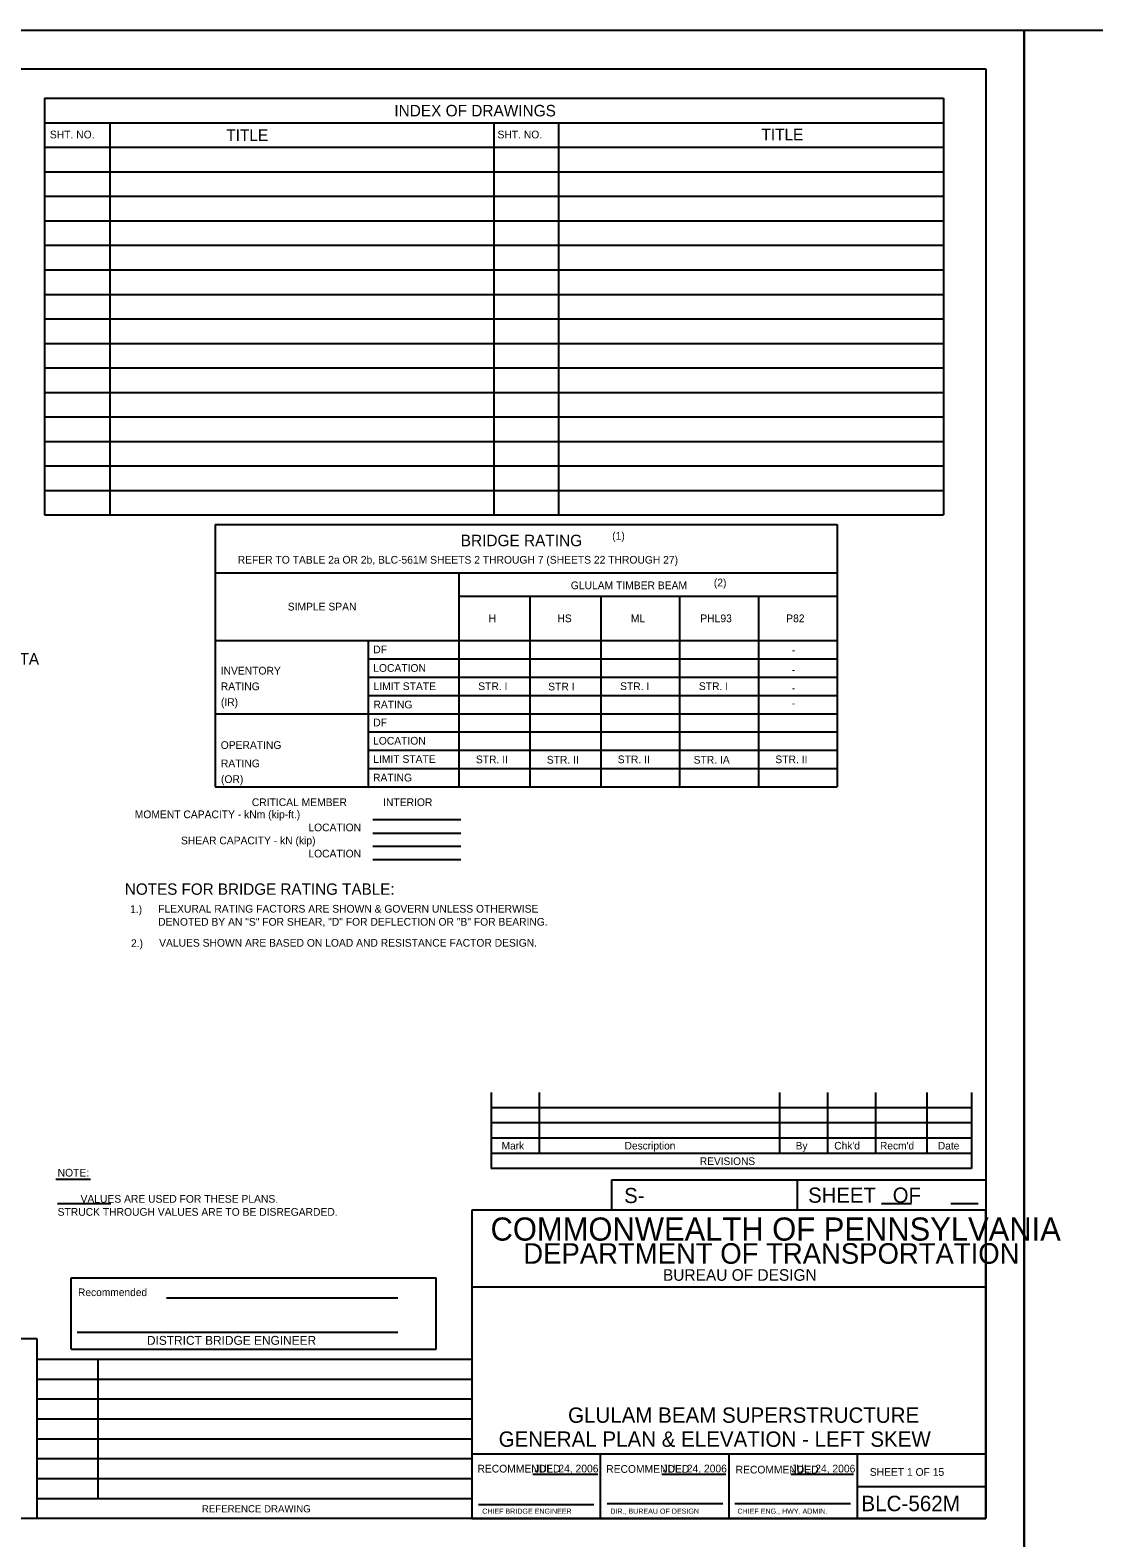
# Model space of a CAD drawing. Extents: x 638263 to 640360, y 293683 to 298655.
# Drawn here: x 638889 to 639304, y 297849 to 298435 of the extents above; entities that cross this region are included whole.
import ezdxf

# ---------------------------------------------------------------- set-up
doc = ezdxf.new("R2010")
doc.units = 0
for name, color, linetype in [('2', 7, 'Continuous'), ('4', 7, 'Continuous'), ('7', 7, 'Continuous'), ('PLT-BNDY', 7, 'Continuous')]:
    doc.layers.add(name, color=color, linetype=linetype)

msp = doc.modelspace()

# ---------------------------------------------------------------- linework, layer by layer
at = {"layer": '2'}
for p, q in [((638475.46, 298420.46), (639261.46, 298420.46)), ((639261.46, 298420.46), (639261.46, 297856.46)), ((639068.92, 298022.15), (639068.92, 297992.62)), ((639087.62, 298022.15), (639087.62, 297998.53)), ((639181.13, 298022.15), (639181.13, 297998.53)), ((639199.83, 298022.15), (639199.83, 297998.53)), ((639218.53, 298022.15), (639218.53, 297998.53)), ((639238.59, 298022.15), (639238.59, 297998.53)), ((639255.94, 298022.15), (639255.94, 297992.62)), ((639255.94, 298016.24), (639068.92, 298016.24)), ((639255.94, 298010.34), (639068.92, 298010.34)), ((639255.94, 298004.43), (639068.92, 298004.43)), ((639255.94, 297998.53), (639068.92, 297998.53)), ((639255.94, 297992.62), (639068.92, 297992.62)), ((638899.44, 297988.52), (638913.01, 297988.52)), ((639261.46, 297988.11), (639115.78, 297988.11)), ((639115.78, 297988.11), (639115.78, 297976.46)), ((639188.09, 297988.11), (639188.09, 297976.46)), ((638900.17, 297979.08), (638920.87, 297979.08)), ((639220.95, 297979), (639232.6, 297979)), ((639247.83, 297979), (639258.56, 297979)), ((639261.46, 297976.46), (639061.46, 297976.46)), ((639061.46, 297976.46), (639061.46, 297856.46)), ((639261.46, 297856.46), (639261.46, 297976.46)), ((638905.4, 297922.31), (638905.4, 297950.1)), ((638905.4, 297950.1), (639047.58, 297950.1)), ((639047.58, 297922.31), (639047.58, 297950.1)), ((638942.6, 297942.38), (639032.62, 297942.38)), ((639261.46, 297946.46), (639061.46, 297946.46)), ((638907.84, 297929.02), (639032.62, 297929.02)), ((638905.4, 297922.31), (639047.58, 297922.31)), ((639261.46, 297881.46), (639061.46, 297881.46)), ((639111.46, 297856.46), (639111.46, 297881.46)), ((639161.46, 297881.46), (639161.46, 297856.46)), ((639211.46, 297881.46), (639211.46, 297856.46)), ((639085.11, 297873.75), (639110.49, 297873.75)), ((639135.38, 297873.75), (639160.27, 297873.75)), ((639185.65, 297873.75), (639210.06, 297873.75)), ((639211.46, 297868.96), (639261.46, 297868.96)), ((639063.96, 297861.96), (639108.96, 297861.96)), ((639114.08, 297862.33), (639159.08, 297862.33)), ((639163.83, 297862.33), (639208.83, 297862.33)), ((639261.46, 297856.46), (638475.46, 297856.46)), ((639061.46, 297856.46), (639261.46, 297856.46))]:
    msp.add_line(p, q, dxfattribs=at)
at = {"layer": '4'}
for p, q in [((638895.05, 298408.97), (639245.05, 298408.97)), ((638895.05, 298408.97), (638895.05, 298246.86)), ((639245.05, 298408.97), (639245.05, 298246.86)), ((638895.05, 298399.44), (639070.05, 298399.44)), ((638920.52, 298399.44), (638920.52, 298246.86)), ((639070.05, 298399.44), (639245.05, 298399.44)), ((639070.05, 298399.44), (639070.05, 298246.86)), ((639095.21, 298399.44), (639095.21, 298246.86)), ((638895.05, 298389.9), (639070.05, 298389.9)), ((639070.05, 298389.9), (639245.05, 298389.9)), ((638895.05, 298380.36), (639070.05, 298380.36)), ((639070.05, 298380.36), (639245.05, 298380.36)), ((638895.05, 298370.83), (639070.05, 298370.83)), ((639070.05, 298370.83), (639245.05, 298370.83)), ((638895.05, 298361.29), (639070.05, 298361.29)), ((639070.05, 298361.29), (639245.05, 298361.29)), ((638895.05, 298351.76), (639070.05, 298351.76)), ((639070.05, 298351.76), (639245.05, 298351.76)), ((638895.05, 298342.22), (639070.05, 298342.22)), ((639070.05, 298342.22), (639245.05, 298342.22)), ((638895.05, 298332.68), (639070.05, 298332.68)), ((639070.05, 298332.68), (639245.05, 298332.68)), ((638895.05, 298323.15), (639070.05, 298323.15)), ((639070.05, 298323.15), (639245.05, 298323.15)), ((638895.05, 298313.61), (639070.05, 298313.61)), ((639070.05, 298313.61), (639245.05, 298313.61)), ((638895.05, 298304.08), (639070.05, 298304.08)), ((639070.05, 298304.08), (639245.05, 298304.08)), ((638895.05, 298294.54), (639070.05, 298294.54)), ((639070.05, 298294.54), (639245.05, 298294.54)), ((638895.05, 298285.01), (639070.05, 298285.01)), ((639070.05, 298285.01), (639245.05, 298285.01)), ((638895.05, 298275.47), (639070.05, 298275.47)), ((639070.05, 298275.47), (639245.05, 298275.47)), ((638895.05, 298265.93), (639070.05, 298265.93)), ((639070.05, 298265.93), (639245.05, 298265.93)), ((638895.05, 298256.4), (639070.05, 298256.4)), ((639070.05, 298256.4), (639245.05, 298256.4)), ((638895.05, 298246.86), (639245.05, 298246.86)), ((639021.04, 298190.91), (639203.67, 298190.91)), ((639021.04, 298183.8), (639203.67, 298183.8)), ((639021.04, 298176.68), (639203.67, 298176.68)), ((639021.04, 298162.45), (639203.67, 298162.45)), ((639021.04, 298155.33), (639203.67, 298155.33)), ((639021.04, 298148.22), (639203.67, 298148.22)), ((639022.83, 298128.43), (639057.1, 298128.43)), ((639022.83, 298123.11), (639057.1, 298123.11)), ((639022.83, 298118.06), (639057.1, 298118.06)), ((639022.83, 298112.88), (639057.1, 298112.88)), ((638892.25, 297926.31), (638754.05, 297926.31)), ((638892.25, 297856.46), (638892.25, 297926.31)), ((639061.46, 297918.34), (638892.25, 297918.34)), ((638915.96, 297864.19), (638915.96, 297918.34)), ((639061.46, 297910.6), (638892.25, 297910.6)), ((639061.46, 297902.87), (638892.25, 297902.87)), ((639061.46, 297895.13), (638892.25, 297895.13)), ((639061.46, 297887.4), (638892.25, 297887.4)), ((639061.46, 297879.66), (638892.25, 297879.66)), ((639061.46, 297871.93), (638892.25, 297871.93)), ((639061.46, 297864.19), (638892.25, 297864.19))]:
    msp.add_line(p, q, dxfattribs=at)
at = {"layer": '7'}
for p, q in [((638961.55, 298243.11), (638961.55, 298141.1)), ((638961.55, 298243.11), (639203.67, 298243.11)), ((639203.67, 298243.11), (639203.67, 298141.1)), ((638961.55, 298224.41), (639203.67, 298224.41)), ((639056.4, 298224.41), (639056.4, 298141.1)), ((639056.4, 298215.21), (639203.67, 298215.21)), ((639084.01, 298215.21), (639084.01, 298141.1)), ((639111.62, 298215.21), (639111.62, 298141.1)), ((639142.31, 298215.21), (639142.31, 298141.1)), ((639172.99, 298215.21), (639172.99, 298141.1)), ((638961.55, 298198.03), (639203.67, 298198.03)), ((639021.04, 298198.03), (639021.04, 298141.1)), ((638961.55, 298169.56), (639203.67, 298169.56)), ((638961.55, 298141.1), (639203.67, 298141.1))]:
    msp.add_line(p, q, dxfattribs=at)
at = {"layer": 'PLT-BNDY'}
for points in [[(638435.46, 298435.46), (639276.46, 298435.46), (639276.46, 297841.46), (638435.46, 297841.46)], [(639276.46, 298435.46), (640117.46, 298435.46), (640117.46, 297841.46), (639276.46, 297841.46)]]:
    msp.add_lwpolyline(points, close=True, dxfattribs=at)

# ---------------------------------------------------------------- texts
at = {"layer": '2'}
for s, height, p in [('MOMENT CAPACITY - kNm (kip-ft.)', 3, (638930.2, 298128.9)), ('LOCATION', 3, (638997.8, 298123.81)), ('SHEAR CAPACITY - kN (kip)', 3, (638948.2, 298118.73)), ('LOCATION', 3, (638997.8, 298113.64)), ('Mark', 2.952, (639073.02, 298000.03)), ('Description', 2.9523, (639120.92, 298000.03)), ('By', 2.952, (639187.49, 298000.03)), ("Chk'd", 2.952, (639202.52, 298000.03)), ("Recm'd", 2.953, (639220.33, 298000.03)), ('Date', 2.952, (639242.86, 298000.03)), ('REVISIONS', 2.952, (639150.2, 297994.01)), ('NOTE:', 3, (638900.18, 297989.5)), ('S-', 5.905, (639120.73, 297979.17)), ('STRUCK THROUGH VALUES ARE TO BE DISREGARDED.', 3, (638900.18, 297974.25)), ('        VALUES ARE USED FOR THESE PLANS.  ', 3, (638900.18, 297979.33)), ('COMMONWEALTH OF PENNSYLVANIA', 9, (639068.71, 297964.58)), ('DEPARTMENT OF TRANSPORTATION', 8.0002, (639081.46, 297955.58)), ('BUREAU OF DESIGN', 4.5, (639135.83, 297948.96)), ('Recommended', 2.9682, (638908.11, 297943)), ('GENERAL PLAN & ELEVATION - LEFT SKEW', 5.9728, (639071.87, 297884.37)), ('RECOMMENDED', 3, (639063.61, 297874.37)), ('JUL. 24, 2006', 3, (639085.74, 297874.4)), ('RECOMMENDED', 3, (639113.74, 297874.25)), ('JUL. 24, 2006', 3, (639135.74, 297874.4)), ('RECOMMENDED', 3, (639164.11, 297874)), ('JUL. 24, 2006', 3, (639185.74, 297874.4)), ('SHEET 1 OF 15', 3, (639216.33, 297873.08)), ('CHIEF BRIDGE ENGINEER', 2.0002, (639065.46, 297858.33)), ('DIR., BUREAU OF DESIGN', 2.0002, (639115.33, 297858.33)), ('CHIEF ENG., HWY. ADMIN.', 2.0002, (639164.83, 297858.33)), ('BLC-562M', 6, (639213.08, 297859.33))]:
    msp.add_text(s, height=height, dxfattribs=at).set_placement(p)
for s, height, rotation, p in [('SHEET   OF', 5.907, 360, (639192.35, 297979.31)), ('DISTRICT BRIDGE ENGINEER', 3.4629, 359.99999, (638934.95, 297924.04))]:
    msp.add_text(s, height=height, rotation=rotation, dxfattribs=at).set_placement(p)
at = {"layer": '4'}
for s, height, p in [('INDEX OF DRAWINGS', 4.4792, (639031.26, 298401.91)), ('SHT. NO.', 3, (638897.16, 298393.36)), ('TITLE', 4.479, (638965.83, 298392.37)), ('SHT. NO.', 3, (639071.42, 298393.36)), ('TITLE', 4.479, (639174.17, 298392.63)), ('BRIDGE RATING', 4.4792, (639057.11, 298234.7)), ('(1)', 3, (639116.06, 298237.25)), ('REFER TO TABLE 2a OR 2b, BLC-561M SHEETS 2 THROUGH 7 (SHEETS 22 THROUGH 27)', 3, (638970.28, 298227.93)), ('GLULAM TIMBER BEAM', 3, (639099.95, 298217.98)), ('(2)', 3, (639155.64, 298219.05)), ('SIMPLE SPAN', 3, (638989.75, 298209.71)), ('H', 3, (639067.96, 298205.15)), ('HS', 3, (639094.73, 298205.15)), ('ML', 3, (639123.32, 298205.15)), ('PHL93', 3, (639150.37, 298205.15)), ('P82', 3, (639183.81, 298205.15)), ('DF', 3, (639023.05, 298193.04)), ('HYDRAULIC DATA', 4.4292, (638841.27, 298188.69)), ('LOCATION', 3, (639023.05, 298185.85)), ('-', 3, (639186, 298192.82)), ('INVENTORY', 3, (638963.66, 298184.8)), ('-', 3, (639186, 298185.21)), ('RATING', 3, (638963.7, 298178.7)), ('LIMIT STATE', 3, (639023.16, 298178.74)), ('STR. I', 3, (639063.91, 298178.74)), ('STR I', 3, (639091.15, 298178.61)), ('STR. I', 3, (639119.13, 298178.75)), ('STR. I', 3, (639149.81, 298178.75)), ('-', 3, (639186, 298178.1)), ('(IR)', 3, (638963.74, 298172.59)), ('RATING', 3, (639023.13, 298171.62)), ('-', 3, (639186, 298172.19)), ('DF', 3, (639023.05, 298164.63)), ('LOCATION', 3, (639022.98, 298157.52)), ('OPERATING', 3, (638963.67, 298155.85)), ('LIMIT STATE', 3, (639023.06, 298150.41)), ('STR. II', 3, (639063, 298150.28)), ('STR. II', 3, (639090.61, 298150.15)), ('STR. II', 3, (639118.22, 298150.29)), ('STR. IA', 3, (639147.77, 298150.12)), ('STR. II', 3, (639179.59, 298150.29)), ('RATING', 3, (638963.74, 298148.71)), ('(OR)', 3, (638963.78, 298142.6)), ('RATING', 3, (639022.98, 298143.2)), ('CRITICAL MEMBER', 3, (638975.78, 298133.62)), ('INTERIOR', 3, (639026.91, 298133.62)), ('NOTES FOR BRIDGE RATING TABLE:', 4.4292, (638926.37, 298099.11)), ('1.)', 3, (638928.38, 298092.02)), ('FLEXURAL RATING FACTORS ARE SHOWN & GOVERN UNLESS OTHERWISE', 3, (638939.33, 298092.17)), ('DENOTED BY AN "S" FOR SHEAR, "D" FOR DEFLECTION OR "B" FOR BEARING.', 3, (638939.33, 298087.09)), ('2.)', 3, (638928.74, 298078.78)), ('VALUES SHOWN ARE BASED ON LOAD AND RESISTANCE FACTOR DESIGN.', 3, (638939.69, 298078.92)), ('GLULAM BEAM SUPERSTRUCTURE', 5.9728, (639098.89, 297893.71))]:
    msp.add_text(s, height=height, dxfattribs=at).set_placement(p)
msp.add_text('REFERENCE DRAWING', height=2.8082, rotation=360, dxfattribs=at).set_placement((638956.34, 297858.86))

doc.saveas('drawing.dxf')
